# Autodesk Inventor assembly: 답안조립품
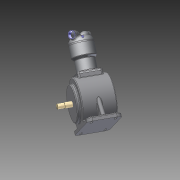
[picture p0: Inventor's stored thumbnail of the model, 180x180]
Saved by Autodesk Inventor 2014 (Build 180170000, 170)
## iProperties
Created: 2015-06
Part Number: 답안조립품
Document SubType Name: Assembly
Designer: user
Author: user
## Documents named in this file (11)
- C:\Users\user\Desktop\450606v1037\답안조립품.iam
- C:\Users\user\Desktop\450606v1037\본체.ipt
- C:\Users\user\Desktop\450606v1037\베어링 6204.ipt
- C:\Users\user\Desktop\450606v1037\메인 크랭크 축-구동부.ipt
- C:\Users\user\Desktop\450606v1037\크랭크 서브축.ipt
- C:\Users\user\Desktop\450606v1037\커넥팅 로드.ipt
- C:\Users\user\Desktop\450606v1037\베어링 NA 4902.ipt
- C:\Users\user\Desktop\450606v1037\피스톤 핀.ipt
- C:\Users\user\Desktop\450606v1037\피스톤.ipt
- C:\Users\user\Desktop\450606v1037\실린더.ipt
- C:\Users\user\Desktop\450606v1037\실린더헤드.ipt
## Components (2 placed, 2 different names)
1. 피스톤 핀:1 — Mate:1, Mate:2, Mate:3
2. 피스톤:1 — Tangent:1, Mate:1, Mate:2, Mate:4, Mate:5
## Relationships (6: Mate 5, Tangent 1)
- Tangent:1: 피스톤:1
- Mate:1: 피스톤 핀:1 ↔ 피스톤:1
- Mate:2: 피스톤 핀:1 ↔ 피스톤:1
- Mate:3: 피스톤 핀:1
- Mate:4: 피스톤:1
- Mate:5: 피스톤:1
